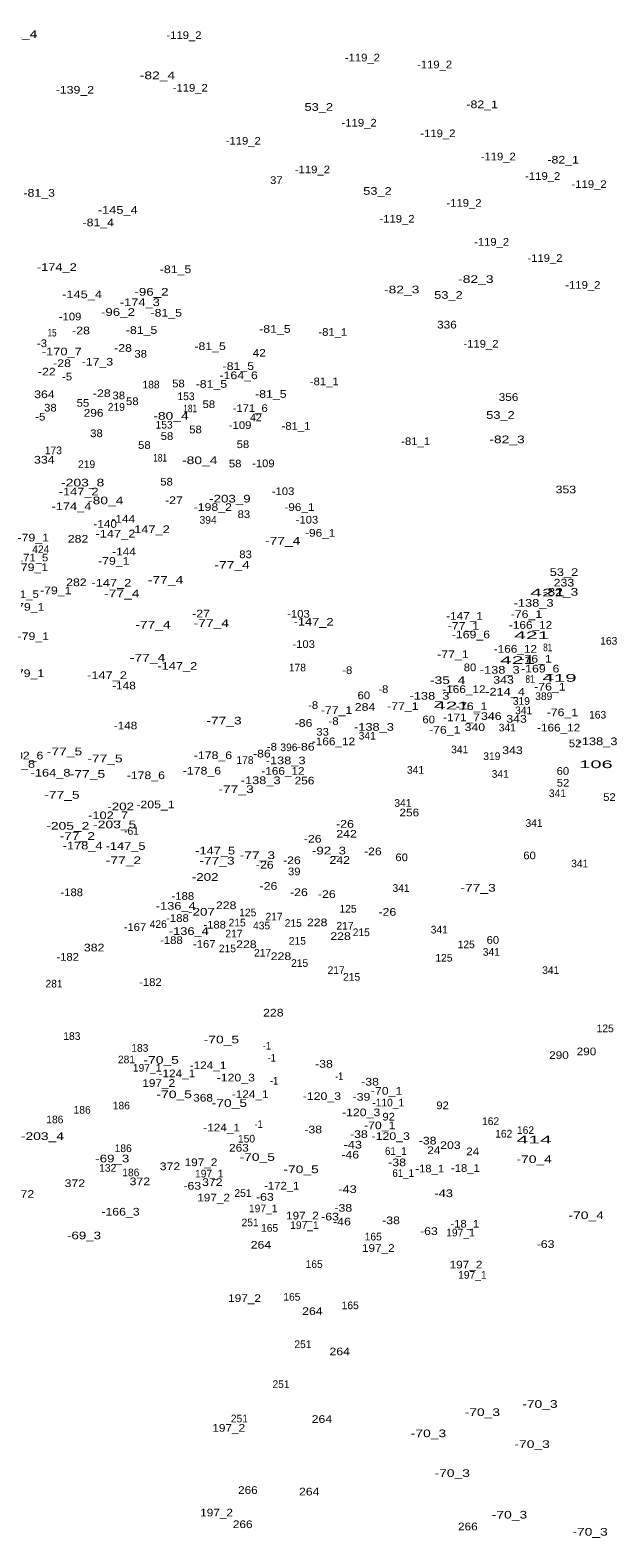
# Model space of a CAD drawing. Extents: x -658110 to -655750, y -1000429 to -997657.
# Drawn here: x -657003 to -656702, y -999113 to -998326 of the extents above; entities that cross this region are included whole.
import ezdxf
from ezdxf.enums import TextEntityAlignment as Align

# ---------------------------------------------------------------- set-up
doc = ezdxf.new("R2010")
doc.units = 0
doc.header["$LTSCALE"] = 1.6
doc.layers.add('24', color=7, linetype='Continuous')

msp = doc.modelspace()

# ---------------------------------------------------------------- texts
at = {"layer": '24'}
for s, width, p in [('-82_4', 1.35, (-657008.49, -998330.12)), ('-119_2', 1.1, (-656922.731, -998330.67)), ('-119_2', 1.1, (-656829.62, -998342.36)), ('-119_2', 1.1, (-656791.981, -998346)), ('-139_2', 1.2, (-656979.65, -998359.19)), ('-82_4', 1.35, (-656936.57, -998351.65)), ('-119_2', 1.1, (-656919.471, -998358.14)), ('-82_1', 1.2, (-656767.16, -998366.79)), ('53_2', 1.25, (-656852.4, -998368.16)), ('-119_2', 1.1, (-656831.341, -998376.38)), ('-119_2', 1.1, (-656790.25, -998381.92)), ('-119_2', 1.1, (-656891.821, -998385.8)), ('-119_2', 1.1, (-656758.76, -998394.02)), ('-82_1', 1.2, (-656724.9, -998395.69)), ('37', 1.1, (-656874.53, -998406.36)), ('-119_2', 1.1, (-656855.721, -998400.78)), ('-119_2', 1.1, (-656735.53, -998404.2)), ('-81_3', 1.2, (-656998.29, -998413.02)), ('53_2', 1.25, (-656821.77, -998411.99)), ('-119_2', 1.1, (-656711.341, -998408.43)), ('-145_4', 1.25, (-656957.29, -998421.89)), ('-119_2', 1.1, (-656776.62, -998418.22)), ('-81_4', 1.2, (-656967.459, -998428.44)), ('-119_2', 1.1, (-656811.561, -998426.52)), ('-119_2', 1.1, (-656762.221, -998438.58)), ('-174_2', 1.25, (-656989.08, -998451.74)), ('-81_5', 1.2, (-656927.13, -998452.9)), ('-119_2', 1.1, (-656734.38, -998447.03)), ('-82_3', 1.35, (-656770.449, -998458.01)), ('-119_2', 1.1, (-656714.601, -998461.05)), ('-145_4', 1.25, (-656975.91, -998465.96)), ('-96_2', 1.3, (-656939.7, -998464.65)), ('-82_3', 1.35, (-656809.12, -998463.44)), ('53_2', 1.25, (-656784.74, -998466.29)), ('-96_2', 1.3, (-656957.18, -998475.22)), ('-174_3', 1.25, (-656945.78, -998470.09)), ('-81_5', 1.2, (-656931.98, -998475.59)), ('-109', 1.1, (-656982.16, -998477.57)), ('-28', 1.2, (-656976.46, -998484.84)), ('-81_5', 1.2, (-656944.87, -998484.61)), ('-81_5', 1.2, (-656875.28, -998484.04)), ('336', 1.15, (-656785.53, -998481.79)), ('-3', 1.1, (-656996.82, -998491.51)), ('15', 0.8, (-656991.579, -998485.97)), ('-81_5', 1.2, (-656909.1, -998493.05)), ('-81_1', 1.1, (-656845.079, -998485.62)), ('-119_2', 1.1, (-656767.78, -998491.76)), ('-170_7', 1.25, (-656986.48, -998495.81)), ('-28', 1.2, (-656954.55, -998493.95)), ('38', 1.1, (-656945.329, -998497)), ('42', 1.15, (-656883.439, -998496.47)), ('-22', 1.2, (-656994.3, -998506.32)), ('-28', 1.2, (-656986.35, -998501.9)), ('-17_3', 1.2, (-656967.9, -998501.15)), ('-164_6', 1.2, (-656894.22, -998508.23)), ('-81_5', 1.2, (-656894.37, -998503.43)), ('-5', 1.1, (-656983.73, -998508.89)), ('58', 1.1, (-656925.62, -998512.49)), ('-81_5', 1.2, (-656908.429, -998512.74)), ('-81_1', 1.1, (-656849.54, -998511.41)), ('364', 1.2, (-656995.55, -998518.15)), ('55', 1.1, (-656975.449, -998522.61)), ('-28', 1.2, (-656965.6, -998517.61)), ('38', 1.1, (-656956.76, -998518.72)), ('58', 1.1, (-656949.689, -998521.78)), ('58', 1.1, (-656909.76, -998523.33)), ('-81_5', 1.2, (-656877.41, -998517.98)), ('356', 1.15, (-656753.38, -998519.59)), ('-5', 1.1, (-656997.69, -998529.84)), ('38', 1.1, (-656992.439, -998525.13)), ('296', 1.15, (-656969.9, -998527.84)), ('-80_4', 1.35, (-656929.53, -998529.42)), ('181', 0.8, (-656919.48, -998525.54)), ('-171_6', 1.1, (-656888.19, -998525.37)), ('53_2', 1.25, (-656757.6, -998528.94)), ('38', 1.1, (-656968.4, -998538.5)), ('58', 1.1, (-656931.61, -998539.96)), ('58', 1.1, (-656916.72, -998536.49)), ('-109', 1.1, (-656893.43, -998534.22)), ('-81_1', 1.1, (-656864.27, -998534.68)), ('58', 1.1, (-656943.41, -998544.61)), ('58', 1.1, (-656891.97, -998544.22)), ('-81_1', 1.1, (-656801.85, -998542.63)), ('-82_3', 1.35, (-656754.16, -998541.67)), ('334', 1.2, (-656995.63, -998552.29)), ('181', 0.8, (-656935.19, -998551.25)), ('-80_4', 1.35, (-656914.51, -998552.59)), ('58', 1.1, (-656896.03, -998554.29)), ('-109', 1.1, (-656881.33, -998554.19)), ('58', 1.1, (-656931.809, -998563.76)), ('-147_2', 1.25, (-656977.69, -998568.9)), ('-203_8', 1.35, (-656975.579, -998564.23)), ('-103', 1.1, (-656871.051, -998568.74)), ('353', 1.2, (-656723.449, -998567.82)), ('-174_4', 1.25, (-656981.459, -998576.58)), ('-80_4', 1.35, (-656963.56, -998573.54)), ('-27', 1.2, (-656927.971, -998573.45)), ('-198_2', 1.2, (-656907.711, -998577.01)), ('-203_9', 1.3, (-656898.77, -998572.62)), ('-96_1', 1.15, (-656862.5, -998577.02)), ('-140', 1.15, (-656963.86, -998585.81)), ('-144', 1.15, (-656954.39, -998583.17)), ('83', 1.1, (-656891.49, -998580.72)), ('-103', 1.1, (-656858.571, -998583.62)), ('-79_1', 1.2, (-657001.4, -998592.93)), ('282', 1.2, (-656978, -998593.57)), ('-147_2', 1.25, (-656958.49, -998590.9)), ('-147_2', 1.25, (-656940.54, -998588.6)), ('-77_4', 1.35, (-656871.231, -998594.62)), ('-96_1', 1.15, (-656851.65, -998590.46)), ('-144', 1.15, (-656954, -998600.27)), ('83', 1.1, (-656890.61, -998601.68)), ('-171_5', 1.1, (-657002.721, -998603.37)), ('-79_1', 1.2, (-657001.83, -998608.42)), ('-79_1', 1.2, (-656959.38, -998605.12)), ('-77_4', 1.35, (-656897.63, -998607.2)), ('53_2', 1.25, (-656724.45, -998610.96)), ('282', 1.2, (-656978.87, -998616.28)), ('-147_2', 1.25, (-656960.6, -998616.54)), ('-77_4', 1.35, (-656932.351, -998615.03)), ('233', 1.2, (-656724.49, -998616.46)), ('-171_5', 1.1, (-657007.66, -998622.48)), ('-79_1', 1.2, (-656989.65, -998620.5)), ('-77_4', 1.35, (-656955.16, -998622.1)), ('421', 2.05, (-656732.913, -998621.65)), ('-82_3', 1.35, (-656726.23, -998621.26)), ('-79_1', 1.2, (-657003.77, -998629.11)), ('-27', 1.2, (-656913.821, -998632.6)), ('-103', 1.1, (-656862.981, -998632.71)), ('-147_1', 1.15, (-656776.34, -998633.82)), ('-76_1', 1.2, (-656744.04, -998632.9)), ('-138_3', 1.25, (-656740.29, -998627.04)), ('-77_4', 1.35, (-656938.921, -998638.42)), ('-77_4', 1.35, (-656908.461, -998637.57)), ('-147_2', 1.25, (-656855.1, -998636.9)), ('-77_1', 1.2, (-656776.92, -998639.01)), ('-166_12', 1.15, (-656741.88, -998638.54)), ('-79_1', 1.2, (-657001.35, -998644.4)), ('-103', 1.1, (-656860.291, -998648.55)), ('-169_6', 1.2, (-656773.01, -998643.51)), ('421', 2.05, (-656741.263, -998643.92)), ('81', 0.8, (-656732.939, -998650.27)), ('-77_4', 1.35, (-656941.731, -998655.64)), ('-77_1', 1.2, (-656782.42, -998653.83)), ('-166_12', 1.15, (-656749.82, -998651.04)), ('421', 2.05, (-656748.643, -998656.88)), ('-76_1', 1.2, (-656739.01, -998656.2)), ('-79_1', 1.2, (-657003.87, -998663.75)), ('-147_2', 1.25, (-656962.91, -998664.76)), ('-147_2', 1.25, (-656926.23, -998659.96)), ('-8', 1.1, (-656837.51, -998662.14)), ('80', 1.1, (-656773.49, -998660.68)), ('-138_3', 1.25, (-656757.98, -998661.98)), ('-169_6', 1.2, (-656736.84, -998661.34)), ('419', 2, (-656726.798, -998666.19)), ('-148', 1.15, (-656954.03, -998670.18)), ('-8', 1.1, (-656818.7, -998672.03)), ('-35_4', 1.35, (-656785.15, -998667.38)), ('-166_12', 1.15, (-656776.67, -998672.08)), ('-214_4', 1.25, (-656755.15, -998673.38)), ('343', 1.2, (-656755.97, -998667.2)), ('81', 0.8, (-656742.16, -998666.75)), ('-76_1', 1.2, (-656731.81, -998670.76)), ('-8', 1.1, (-656855.35, -998680.37)), ('284', 1.2, (-656828.26, -998681.36)), ('60', 1.1, (-656828.89, -998675.27)), ('-77_1', 1.2, (-656808.53, -998680.9)), ('-138_3', 1.25, (-656794.62, -998675.54)), ('421', 2.05, (-656783.133, -998680.61)), ('-76_1', 1.2, (-656772.66, -998680.98)), ('-77_3', 1.35, (-656901.851, -998688.47)), ('-86', 1.2, (-656860.36, -998689.71)), ('-77_1', 1.2, (-656843.15, -998683.02)), ('-8', 1.1, (-656844.68, -998688.71)), ('60', 1.1, (-656795.03, -998687.87)), ('-171_7', 1.15, (-656777.97, -998686.79)), ('346', 1.2, (-656762.37, -998686.11)), ('343', 1.2, (-656749.179, -998687.56)), ('-76_1', 1.2, (-656725.28, -998684.16)), ('-148', 1.15, (-656953.26, -998691.03)), ('33', 1.1, (-656850.4, -998694.31)), ('-138_3', 1.25, (-656823.61, -998691.77)), ('-76_1', 1.2, (-656786.68, -998693.26)), ('340', 1.2, (-656770.959, -998691.92)), ('-166_12', 1.15, (-656727.25, -998692.15)), ('-77_5', 1.35, (-656985.081, -998704.57)), ('-8', 1.1, (-656876.86, -998702.09)), ('-86', 1.2, (-656859.2, -998702.13)), ('-166_12', 1.15, (-656844.72, -998699.32)), ('343', 1.2, (-656751.319, -998703.95)), ('52', 1.1, (-656718.65, -998700.36)), ('-138_3', 1.25, (-656706.959, -998699.28)), ('-164_8', 1.25, (-657010.86, -998711.08)), ('-102_6', 1.2, (-657006.101, -998706.69)), ('-77_5', 1.35, (-656963.99, -998708.25)), ('-178_6', 1.2, (-656907.61, -998706.54)), ('-86', 1.2, (-656882.08, -998705.71)), ('-138_3', 1.25, (-656869.689, -998709.25)), ('106', 1.95, (-656707.759, -998711.27)), ('-164_8', 1.25, (-656992.38, -998715.68)), ('-77_5', 1.35, (-656973.081, -998716.28)), ('-178_6', 1.2, (-656942.65, -998717.01)), ('-178_6', 1.2, (-656913.37, -998714.61)), ('-138_3', 1.25, (-656882.72, -998719.63)), ('-166_12', 1.15, (-656871.09, -998714.74)), ('256', 1.15, (-656859.83, -998719.76)), ('60', 1.1, (-656725.02, -998714.76)), ('52', 1.1, (-656724.949, -998720.92)), ('-77_5', 1.35, (-656986.431, -998727.21)), ('-77_3', 1.35, (-656895.571, -998724.26)), ('52', 1.1, (-656700.72, -998728.39)), ('-202', 1.3, (-656955.78, -998733.27)), ('-205_1', 1.2, (-656937.61, -998732.25)), ('256', 1.15, (-656805.16, -998736.44)), ('-205_2', 1.35, (-656983.36, -998743.39)), ('-102_7', 1.25, (-656962.341, -998737.9)), ('-203_5', 1.35, (-656958.89, -998742.68)), ('-26', 1.2, (-656838.7, -998742.39)), ('-77_2', 1.35, (-656978.41, -998748.71)), ('-26', 1.2, (-656855.57, -998750.15)), ('242', 1.2, (-656837.88, -998747.57)), ('-178_4', 1.25, (-656975.62, -998753.7)), ('-147_5', 1.25, (-656953.22, -998753.95)), ('-147_5', 1.25, (-656906.46, -998756.35)), ('-77_3', 1.35, (-656884.451, -998758.72)), ('-92_3', 1.3, (-656847.08, -998756.32)), ('-26', 1.2, (-656824.17, -998756.74)), ('60', 1.1, (-656809.14, -998759.84)), ('60', 1.1, (-656742.41, -998758.87)), ('-77_2', 1.35, (-656954.331, -998761.38)), ('-77_3', 1.35, (-656905.53, -998761.6)), ('-26', 1.2, (-656880.57, -998763.72)), ('-26', 1.2, (-656866.44, -998761.39)), ('39', 1.1, (-656865.21, -998767.2)), ('242', 1.2, (-656841.47, -998761.24)), ('-202', 1.3, (-656911.68, -998770.11)), ('-26', 1.2, (-656878.64, -998774.78)), ('-77_3', 1.35, (-656769.28, -998775.74)), ('-188', 1.1, (-656981.311, -998778.11)), ('-188', 1.1, (-656923.331, -998780.02)), ('-26', 1.2, (-656862.75, -998778.07)), ('-26', 1.2, (-656848.21, -998779.04)), ('-136_4', 1.25, (-656927.03, -998785.18)), ('-188', 1.1, (-656926.13, -998791.55)), ('-207', 1.3, (-656913.59, -998788.28)), ('228', 1.2, (-656900.73, -998784.88)), ('-26', 1.2, (-656816.61, -998788.35)), ('-167', 1.1, (-656948.319, -998796.23)), ('-136_4', 1.25, (-656920.2, -998798.34)), ('-188', 1.1, (-656906.731, -998795)), ('228', 1.2, (-656853.24, -998793.8)), ('382', 1.2, (-656969.61, -998806.95)), ('-188', 1.1, (-656929.28, -998803.07)), ('-167', 1.1, (-656912.16, -998805.06)), ('228', 1.2, (-656890.169, -998805.24)), ('228', 1.2, (-656841.02, -998800.98)), ('60', 1.1, (-656761.561, -998802.97)), ('-182', 1.1, (-656983.441, -998811.82)), ('228', 1.2, (-656872.13, -998811.45)), ('-182', 1.1, (-656940.24, -998824.97)), ('228', 1.2, (-656876.11, -998840.93)), ('-70_5', 1.35, (-656903.22, -998854.94)), ('-1', 0.9, (-656879.451, -998858.2)), ('290', 1.15, (-656712.721, -998861.15)), ('-70_5', 1.35, (-656934.63, -998865.61)), ('-124_1', 1.15, (-656910.179, -998868.4)), ('-1', 0.9, (-656876.91, -998864.5)), ('-38', 1.2, (-656849.68, -998867.67)), ('290', 1.15, (-656727.071, -998863.09)), ('197_2', 1.15, (-656935.921, -998877.65)), ('-124_1', 1.15, (-656926.41, -998872.63)), ('-120_3', 1.2, (-656895.699, -998874.81)), ('-1', 0.9, (-656875.671, -998876.43)), ('-1', 0.9, (-656841.74, -998874.1)), ('-38', 1.2, (-656825.64, -998876.98)), ('-70_5', 1.35, (-656927.84, -998883.55)), ('368', 1.15, (-656912.76, -998885.33)), ('-124_1', 1.15, (-656888.199, -998883.48)), ('-120_3', 1.2, (-656850.76, -998884.51)), ('-39', 1.2, (-656830.11, -998884.87)), ('-70_1', 1.2, (-656817.02, -998881.73)), ('-70_5', 1.35, (-656899.05, -998888.1)), ('-120_3', 1.2, (-656830.309, -998892.97)), ('92', 1.1, (-656787.81, -998889.3)), ('-124_1', 1.15, (-656903.079, -998900.87)), ('-1', 0.9, (-656883.811, -998899.12)), ('-38', 1.2, (-656855.31, -998901.9)), ('-70_1', 1.2, (-656820.601, -998899.76)), ('92', 1.1, (-656815.92, -998895.22)), ('-203_4', 1.35, (-656996.6, -998905.38)), ('-43', 1.25, (-656834.68, -998909.84)), ('-38', 1.2, (-656831.46, -998904.33)), ('-120_3', 1.2, (-656814.86, -998905.37)), ('-38', 1.2, (-656795.59, -998907.73)), ('203', 1.2, (-656783.709, -998910.08)), ('414', 2.05, (-656739.989, -998907.19)), ('-69_3', 1.3, (-656960.16, -998917.06)), ('263', 1.15, (-656894.07, -998911.46)), ('-70_5', 1.35, (-656884.51, -998916.3)), ('-46', 1.2, (-656835.99, -998915.06)), ('61_1', 0.95, (-656812.2, -998913.16)), ('24', 1.15, (-656792.37, -998912.75)), ('24', 1.15, (-656772.049, -998913.35)), ('-70_4', 1.35, (-656740, -998917.4)), ('372', 1.2, (-656930.05, -998921.13)), ('197_2', 1.15, (-656913.861, -998919.03)), ('-70_5', 1.35, (-656861.63, -998922.7)), ('-38', 1.2, (-656811.5, -998919.07)), ('61_1', 0.95, (-656808.34, -998924.67)), ('-18_1', 1.1, (-656794.51, -998922.3)), ('-18_1', 1.1, (-656775.9, -998922.01)), ('372', 1.2, (-656979.68, -998929.95)), ('372', 1.2, (-656945.75, -998928.98)), ('-63', 1.2, (-656918.41, -998931.3)), ('372', 1.2, (-656907.95, -998929.37)), ('-172_1', 1.1, (-656871.721, -998931.24)), ('-43', 1.25, (-656837.41, -998933.06)), ('372', 1.2, (-657006.24, -998935.58)), ('197_2', 1.15, (-656907.27, -998937.45)), ('-63', 1.2, (-656880.52, -998937.11)), ('-43', 1.25, (-656787.23, -998935.21)), ('-166_3', 1.2, (-656955.87, -998944.83)), ('197_2', 1.15, (-656860.951, -998946.86)), ('-63', 1.2, (-656846.49, -998947.39)), ('-38', 1.2, (-656839.6, -998942.8)), ('-38', 1.2, (-656814.7, -998949.33)), ('-70_4', 1.35, (-656712.86, -998946.68)), ('-69_3', 1.3, (-656974.89, -998957.21)), ('-46', 1.2, (-656840.28, -998949.98)), ('-63', 1.2, (-656794.93, -998954.95)), ('-18_1', 1.1, (-656776.189, -998951.1)), ('264', 1.2, (-656882.56, -998962.1)), ('197_2', 1.15, (-656821.351, -998963.78)), ('-63', 1.2, (-656734.06, -998961.74)), ('197_2', 1.15, (-656775.591, -998972.44)), ('197_2', 1.15, (-656891.13, -998989.95)), ('264', 1.2, (-656855.71, -998996.72)), ('264', 1.2, (-656841.46, -999017.76)), ('-70_3', 1.35, (-656767.05, -999049.46)), ('-70_3', 1.35, (-656737, -999045.2)), ('197_2', 1.15, (-656899.39, -999057.65)), ('264', 1.2, (-656850.77, -999053.06)), ('-70_3', 1.35, (-656795.17, -999060.52)), ('-70_3', 1.35, (-656741.08, -999066.14)), ('-70_3', 1.35, (-656782.76, -999081.27)), ('266', 1.15, (-656889.39, -999090.13)), ('264', 1.2, (-656857.4, -999090.93)), ('197_2', 1.15, (-656905.731, -999101.87)), ('-70_3', 1.35, (-656752.9, -999102.99)), ('266', 1.15, (-656892.1, -999107.98)), ('266', 1.15, (-656774.62, -999109.14)), ('-70_3', 1.35, (-656710.84, -999111.91))]:
    msp.add_text(s, height=4, dxfattribs=dict(at, width=width)).set_placement(p, align=Align.CENTER)
for s, p in [('188', (-656939.919, -998513.06)), ('153', (-656921.66, -998519.19)), ('219', (-656958.03, -998524.76)), ('42', (-656885.231, -998530.22)), ('153', (-656933.1, -998534.03)), ('173', (-656990.87, -998547.4)), ('219', (-656973.541, -998554.63)), ('394', (-656910.137, -998583.71)), ('424', (-656997.446, -998599.02)), ('163', (-656701.071, -998646.82)), ('178', (-656863.551, -998660.78)), ('319', (-656746.681, -998678.23)), ('389', (-656734.983, -998675.74)), ('341', (-656745.49, -998683.14)), ('163', (-656706.89, -998685.41)), ('341', (-656827.11, -998696.35)), ('341', (-656754.02, -998692.09)), ('396', (-656867.988, -998702.42)), ('341', (-656778.84, -998703.53)), ('178', (-656890.89, -998709.07)), ('319', (-656762.081, -998707.05)), ('341', (-656801.91, -998714.2)), ('341', (-656757.709, -998716.33)), ('341', (-656727.85, -998726.41)), ('341', (-656808.5, -998731.46)), ('341', (-656740.059, -998741.93)), ('-61', (-656950.11, -998746.08)), ('341', (-656716.209, -998763.07)), ('341', (-656809.459, -998775.87)), ('125', (-656889.449, -998788.61)), ('217', (-656875.731, -998790.8)), ('125', (-656837.1, -998786.67)), ('426', (-656936.147, -998794.7)), ('217', (-656896.671, -998799.63)), ('215', (-656894.98, -998793.92)), ('435', (-656882.231, -998795.45)), ('215', (-656865.699, -998794.12)), ('217', (-656838.701, -998795.55)), ('215', (-656830.22, -998798.97)), ('341', (-656789.5, -998797.59)), ('215', (-656900.069, -998807.4)), ('215', (-656863.569, -998803.43)), ('125', (-656775.449, -998805.29)), ('217', (-656881.74, -998809.66)), ('215', (-656862.4, -998815.02)), ('125', (-656787.079, -998812.27)), ('341', (-656762.35, -998809.22)), ('217', (-656843.351, -998818.73)), ('215', (-656835.26, -998822.23)), ('341', (-656731.34, -998818.73)), ('281', (-656990.54, -998825.78)), ('183', (-656981.24, -998853.14)), ('125', (-656702.939, -998849.13)), ('183', (-656945.77, -998859.35)), ('281', (-656952.74, -998865.35)), ('197_1', (-656941.951, -998869.72)), ('186', (-656975.87, -998891.64)), ('186', (-656955.421, -998889.41)), ('-110_1', (-656816.16, -998887.87)), ('186', (-656990.12, -998896.68)), ('162', (-656762.74, -998897.59)), ('162', (-656744.52, -998902.24)), ('150', (-656890.11, -998906.7)), ('162', (-656755.861, -998904.09)), ('186', (-656954.451, -998911.71)), ('132', (-656962.53, -998921.95)), ('186', (-656950.481, -998924.32)), ('197_1', (-656909.551, -998924.93)), ('251', (-656891.959, -998935.07)), ('197_1', (-656881.39, -998943.11)), ('251', (-656888.23, -998950.43)), ('165', (-656878.071, -998953.28)), ('197_1', (-656859.87, -998951.84)), ('197_1', (-656778.451, -998955.71)), ('165', (-656823.981, -998957.82)), ('165', (-656854.811, -998972.18)), ('197_1', (-656772.24, -998977.79)), ('165', (-656866.441, -998989.24)), ('165', (-656836, -998993.7)), ('251', (-656860.66, -999014)), ('251', (-656872.1, -999034.85)), ('251', (-656893.809, -999052.79))]:
    msp.add_text(s, height=4, dxfattribs=at).set_placement(p, align=Align.CENTER)

doc.saveas('drawing.dxf')
